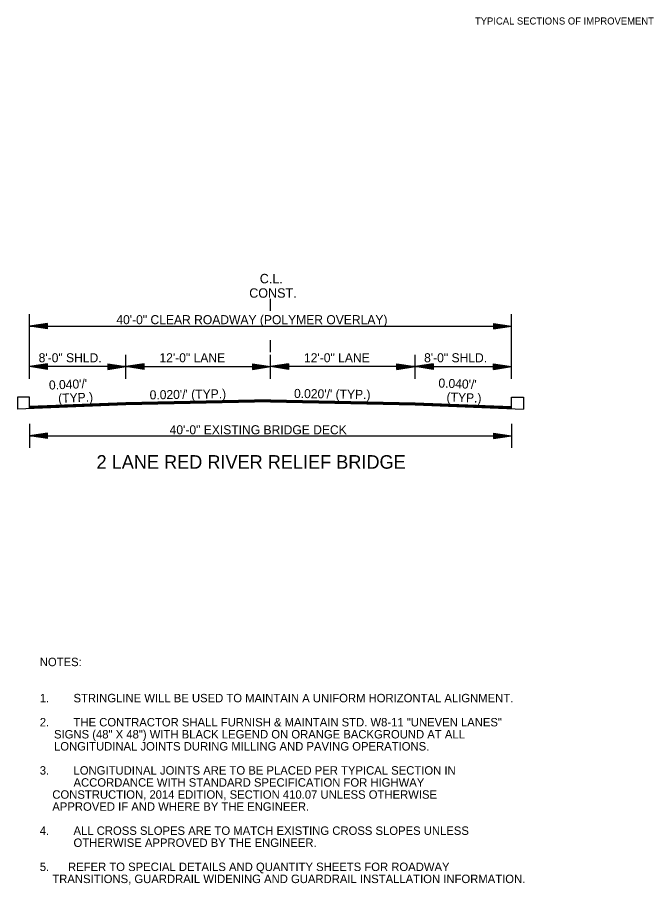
# Model space of a CAD drawing. Extents: x 545241 to 1930787, y -1971772 to 596640.
# Drawn here: x 547727 to 548255, y -1957206 to -1956486 of the extents above; entities that cross this region are included whole.
import ezdxf

# ---------------------------------------------------------------- set-up
doc = ezdxf.new("R2010")
doc.units = 0
for name, color, linetype in [('R_Border', 7, 'Continuous'), ('R_Border Notes', 7, 'Continuous'), ('R_Border Prem', 7, 'Continuous'), ('R_Draft', 7, 'Continuous')]:
    doc.layers.add(name, color=color, linetype=linetype)

msp = doc.modelspace()

# ---------------------------------------------------------------- linework, layer by layer
at = {"layer": 'R_Border'}
for p, q in [((547737.06, -1956801.11), (547726.89, -1956801.11)), ((547726.89, -1956801.11), (547726.89, -1956811.13)), ((547737.06, -1956810.72), (547737.06, -1956801.11)), ((548137.06, -1956801.31), (548147.23, -1956801.31)), ((548137.06, -1956810.72), (548137.06, -1956801.31)), ((548147.23, -1956801.31), (548147.23, -1956811.13))]:
    msp.add_line(p, q, dxfattribs=at)
at = {"layer": 'R_Draft'}
for p, q in [((547937.06, -1956729.59), (547937.06, -1956719.59)), ((547737.06, -1956785.84), (547737.06, -1956732.31)), ((548137.06, -1956785.84), (548137.06, -1956732.31)), ((547752.06, -1956740.06), (547737.06, -1956742.31)), ((547737.06, -1956742.31), (548137.06, -1956742.31)), ((547752.06, -1956744.56), (547737.06, -1956742.31)), ((547752.06, -1956740.43), (547739.56, -1956742.31)), ((547752.06, -1956744.18), (547739.56, -1956742.31)), ((547752.06, -1956740.81), (547742.14, -1956742.31)), ((547752.06, -1956743.8), (547742.14, -1956742.31)), ((547752.06, -1956741.19), (547744.64, -1956742.31)), ((547752.06, -1956743.42), (547744.64, -1956742.31)), ((547752.06, -1956741.57), (547747.18, -1956742.31)), ((547752.06, -1956743.03), (547747.18, -1956742.31)), ((547752.06, -1956741.95), (547749.69, -1956742.31)), ((547752.06, -1956742.66), (547749.69, -1956742.31)), ((547752.06, -1956744.56), (547752.06, -1956740.06)), ((548122.06, -1956740.06), (548137.06, -1956742.31)), ((548122.06, -1956740.06), (548122.06, -1956744.56)), ((548122.06, -1956740.43), (548134.55, -1956742.31)), ((548122.06, -1956740.81), (548131.97, -1956742.31)), ((548122.06, -1956741.19), (548129.48, -1956742.31)), ((548122.06, -1956741.58), (548126.93, -1956742.31)), ((548122.06, -1956741.95), (548124.43, -1956742.31)), ((548122.06, -1956744.56), (548137.06, -1956742.31)), ((548122.06, -1956743.04), (548126.93, -1956742.31)), ((548122.06, -1956743.8), (548131.97, -1956742.31)), ((548122.06, -1956744.18), (548134.55, -1956742.31)), ((548122.06, -1956743.42), (548129.48, -1956742.31)), ((548122.06, -1956742.66), (548124.43, -1956742.31)), ((547937.06, -1956763.83), (547937.06, -1956753.96)), ((547817.06, -1956785.84), (547817.06, -1956765.95)), ((547937.06, -1956785.84), (547937.06, -1956765.95)), ((548057.06, -1956785.84), (548057.06, -1956765.95)), ((547752.06, -1956773.59), (547737.06, -1956775.84)), ((547817.06, -1956775.84), (547737.06, -1956775.84)), ((547752.06, -1956778.09), (547737.06, -1956775.84)), ((547752.06, -1956773.97), (547739.56, -1956775.84)), ((547752.06, -1956777.72), (547739.56, -1956775.84)), ((547752.06, -1956774.35), (547742.14, -1956775.84)), ((547752.06, -1956777.33), (547742.14, -1956775.84)), ((547752.06, -1956774.72), (547744.64, -1956775.84)), ((547752.06, -1956776.96), (547744.64, -1956775.84)), ((547752.06, -1956775.11), (547747.18, -1956775.84)), ((547752.06, -1956776.57), (547747.18, -1956775.84)), ((547752.06, -1956775.49), (547749.69, -1956775.84)), ((547752.06, -1956776.19), (547749.69, -1956775.84)), ((547752.06, -1956778.09), (547752.06, -1956773.59)), ((547802.06, -1956773.59), (547817.06, -1956775.84)), ((547802.06, -1956773.59), (547802.06, -1956778.09)), ((547802.06, -1956773.97), (547814.55, -1956775.84)), ((547802.06, -1956774.35), (547811.97, -1956775.84)), ((547802.06, -1956774.72), (547809.48, -1956775.84)), ((547802.06, -1956775.11), (547806.93, -1956775.84)), ((547802.06, -1956775.49), (547804.43, -1956775.84)), ((547802.06, -1956778.09), (547817.06, -1956775.84)), ((547802.06, -1956776.58), (547806.93, -1956775.84)), ((547802.06, -1956777.33), (547811.97, -1956775.84)), ((547802.06, -1956777.72), (547814.55, -1956775.84)), ((547802.06, -1956776.96), (547809.48, -1956775.84)), ((547802.06, -1956776.19), (547804.43, -1956775.84)), ((547832.06, -1956773.59), (547817.06, -1956775.84)), ((547832.06, -1956778.09), (547817.06, -1956775.84)), ((547817.06, -1956775.84), (547937.06, -1956775.84)), ((547832.06, -1956773.97), (547819.56, -1956775.84)), ((547832.06, -1956777.72), (547819.56, -1956775.84)), ((547832.06, -1956774.35), (547822.14, -1956775.84)), ((547832.06, -1956777.33), (547822.14, -1956775.84)), ((547832.06, -1956774.72), (547824.64, -1956775.84)), ((547832.06, -1956776.96), (547824.64, -1956775.84)), ((547832.06, -1956775.11), (547827.18, -1956775.84)), ((547832.06, -1956776.57), (547827.18, -1956775.84)), ((547832.06, -1956775.49), (547829.69, -1956775.84)), ((547832.06, -1956776.19), (547829.69, -1956775.84)), ((547832.06, -1956778.09), (547832.06, -1956773.59)), ((547922.06, -1956773.59), (547937.06, -1956775.84)), ((547922.06, -1956773.59), (547922.06, -1956778.09)), ((547922.06, -1956773.97), (547934.55, -1956775.84)), ((547922.06, -1956774.35), (547931.97, -1956775.84)), ((547922.06, -1956774.72), (547929.48, -1956775.84)), ((547922.06, -1956775.11), (547926.93, -1956775.84)), ((547922.06, -1956775.49), (547924.43, -1956775.84)), ((547922.06, -1956778.09), (547937.06, -1956775.84)), ((547922.06, -1956776.58), (547926.93, -1956775.84)), ((547922.06, -1956777.33), (547931.97, -1956775.84)), ((547922.06, -1956777.72), (547934.55, -1956775.84)), ((547922.06, -1956776.96), (547929.48, -1956775.84)), ((547922.06, -1956776.19), (547924.43, -1956775.84)), ((547952.06, -1956773.59), (547937.06, -1956775.84)), ((548057.06, -1956775.84), (547937.06, -1956775.84)), ((547952.06, -1956778.09), (547937.06, -1956775.84)), ((547952.06, -1956773.97), (547939.56, -1956775.84)), ((547952.06, -1956777.72), (547939.56, -1956775.84)), ((547952.06, -1956774.35), (547942.14, -1956775.84)), ((547952.06, -1956777.33), (547942.14, -1956775.84)), ((547952.06, -1956774.72), (547944.64, -1956775.84)), ((547952.06, -1956776.96), (547944.64, -1956775.84)), ((547952.06, -1956775.11), (547947.18, -1956775.84)), ((547952.06, -1956776.58), (547947.18, -1956775.84)), ((547952.06, -1956775.49), (547949.69, -1956775.84)), ((547952.06, -1956776.19), (547949.69, -1956775.84)), ((547952.06, -1956773.59), (547952.06, -1956778.09)), ((548042.06, -1956773.59), (548057.06, -1956775.84)), ((548042.06, -1956778.09), (548042.06, -1956773.59)), ((548042.06, -1956773.97), (548054.55, -1956775.84)), ((548042.06, -1956774.35), (548051.97, -1956775.84)), ((548042.06, -1956774.72), (548049.48, -1956775.84)), ((548042.06, -1956775.11), (548046.93, -1956775.84)), ((548042.06, -1956775.49), (548044.43, -1956775.84)), ((548042.06, -1956778.09), (548057.06, -1956775.84)), ((548042.06, -1956776.57), (548046.93, -1956775.84)), ((548042.06, -1956777.33), (548051.97, -1956775.84)), ((548042.06, -1956777.72), (548054.55, -1956775.84)), ((548042.06, -1956776.96), (548049.48, -1956775.84)), ((548042.06, -1956776.19), (548044.43, -1956775.84)), ((548072.06, -1956773.59), (548057.06, -1956775.84)), ((548072.06, -1956778.09), (548057.06, -1956775.84)), ((548057.06, -1956775.84), (548137.06, -1956775.84)), ((548072.06, -1956773.97), (548059.56, -1956775.84)), ((548072.06, -1956777.72), (548059.56, -1956775.84)), ((548072.06, -1956774.35), (548062.14, -1956775.84)), ((548072.06, -1956777.33), (548062.14, -1956775.84)), ((548072.06, -1956774.72), (548064.64, -1956775.84)), ((548072.06, -1956776.96), (548064.64, -1956775.84)), ((548072.06, -1956775.11), (548067.18, -1956775.84)), ((548072.06, -1956776.58), (548067.18, -1956775.84)), ((548072.06, -1956775.49), (548069.69, -1956775.84)), ((548072.06, -1956776.19), (548069.69, -1956775.84)), ((548072.06, -1956773.59), (548072.06, -1956778.09)), ((548122.06, -1956773.59), (548137.06, -1956775.84)), ((548122.06, -1956778.09), (548122.06, -1956773.59)), ((548122.06, -1956773.97), (548134.55, -1956775.84)), ((548122.06, -1956774.35), (548131.97, -1956775.84)), ((548122.06, -1956774.72), (548129.48, -1956775.84)), ((548122.06, -1956775.11), (548126.93, -1956775.84)), ((548122.06, -1956775.49), (548124.43, -1956775.84)), ((548122.06, -1956778.09), (548137.06, -1956775.84)), ((548122.06, -1956776.57), (548126.93, -1956775.84)), ((548122.06, -1956777.33), (548131.97, -1956775.84)), ((548122.06, -1956777.72), (548134.55, -1956775.84)), ((548122.06, -1956776.96), (548129.48, -1956775.84)), ((548122.06, -1956776.19), (548124.43, -1956775.84)), ((547817.06, -1956807.52), (547726.89, -1956811.13)), ((547817.06, -1956805.85), (547737.06, -1956809.05)), ((547817.06, -1956806.15), (547737.06, -1956809.35)), ((547817.06, -1956806.45), (547737.06, -1956809.65)), ((547817.06, -1956806.75), (547737.06, -1956809.95)), ((547817.06, -1956807.05), (547737.06, -1956810.25)), ((547817.06, -1956807.35), (547737.06, -1956810.55)), ((547937.06, -1956803.45), (547817.06, -1956805.85)), ((547937.06, -1956803.75), (547817.06, -1956806.15)), ((547937.07, -1956804.05), (547817.06, -1956806.45)), ((547937.08, -1956804.35), (547817.06, -1956806.75)), ((547937.08, -1956804.65), (547817.06, -1956807.05)), ((547937.09, -1956804.95), (547817.06, -1956807.35)), ((547937.09, -1956805.12), (547817.06, -1956807.52)), ((547937.02, -1956805.12), (548057.06, -1956807.52)), ((547937.03, -1956804.65), (548057.06, -1956807.05)), ((547937.03, -1956804.95), (548057.06, -1956807.35)), ((547937.04, -1956804.35), (548057.06, -1956806.75)), ((547937.05, -1956803.75), (548057.06, -1956806.15)), ((547937.05, -1956804.05), (548057.06, -1956806.45)), ((547937.06, -1956803.45), (548057.06, -1956805.85)), ((548057.06, -1956805.85), (548137.06, -1956809.05)), ((548057.06, -1956806.15), (548137.06, -1956809.35)), ((548057.06, -1956806.45), (548137.06, -1956809.65)), ((548057.06, -1956806.75), (548137.06, -1956809.95)), ((548057.06, -1956807.05), (548137.06, -1956810.25)), ((548057.06, -1956807.35), (548137.06, -1956810.55)), ((548057.06, -1956807.52), (548147.23, -1956811.13)), ((547737.06, -1956823.31), (547737.06, -1956843.31)), ((548137.06, -1956823.31), (548137.06, -1956843.31)), ((547752.06, -1956831.06), (547737.06, -1956833.31)), ((547737.06, -1956833.31), (548137.06, -1956833.31)), ((547752.06, -1956835.56), (547737.06, -1956833.31)), ((547752.06, -1956831.43), (547739.56, -1956833.31)), ((547752.06, -1956835.18), (547739.56, -1956833.31)), ((547752.06, -1956831.81), (547742.14, -1956833.31)), ((547752.06, -1956834.8), (547742.14, -1956833.31)), ((547752.06, -1956832.19), (547744.64, -1956833.31)), ((547752.06, -1956834.42), (547744.64, -1956833.31)), ((547752.06, -1956832.57), (547747.18, -1956833.31)), ((547752.06, -1956834.03), (547747.18, -1956833.31)), ((547752.06, -1956832.95), (547749.69, -1956833.31)), ((547752.06, -1956833.66), (547749.69, -1956833.31)), ((547752.06, -1956835.56), (547752.06, -1956831.06)), ((548122.06, -1956831.06), (548137.06, -1956833.31)), ((548122.06, -1956831.06), (548122.06, -1956835.56)), ((548122.06, -1956831.43), (548134.55, -1956833.31)), ((548122.06, -1956831.81), (548131.97, -1956833.31)), ((548122.06, -1956832.19), (548129.48, -1956833.31)), ((548122.06, -1956832.58), (548126.93, -1956833.31)), ((548122.06, -1956832.95), (548124.43, -1956833.31)), ((548122.06, -1956835.56), (548137.06, -1956833.31)), ((548122.06, -1956834.04), (548126.93, -1956833.31)), ((548122.06, -1956834.8), (548131.97, -1956833.31)), ((548122.06, -1956835.18), (548134.55, -1956833.31)), ((548122.06, -1956834.42), (548129.48, -1956833.31)), ((548122.06, -1956833.66), (548124.43, -1956833.31))]:
    msp.add_line(p, q, dxfattribs=at)

# ---------------------------------------------------------------- texts
at = {"layer": 'R_Border Notes'}
for s, p in [('NOTES: ', (547745.53, -1957024.39)), ('1.', (547745.53, -1957054.39)), ('STRINGLINE WILL BE USED TO MAINTAIN A UNIFORM HORIZONTAL ALIGNMENT.', (547773.53, -1957054.39)), ('2.', (547745.53, -1957074.39)), ('THE CONTRACTOR SHALL FURNISH & MAINTAIN STD. W8-11 "UNEVEN LANES" ', (547773.53, -1957074.39)), ('    SIGNS (48" X 48") WITH BLACK LEGEND ON ORANGE BACKGROUND AT ALL ', (547746.93, -1957084.39)), ('    LONGITUDINAL JOINTS DURING MILLING AND PAVING OPERATIONS.', (547746.93, -1957094.39)), ('3.', (547745.53, -1957114.39)), ('LONGITUDINAL JOINTS ARE TO BE PLACED PER TYPICAL SECTION IN ', (547773.53, -1957114.39)), ('ACCORDANCE WITH STANDARD SPECIFICATION FOR HIGHWAY', (547773.53, -1957124.39)), ('    CONSTRUCTION, 2014 EDITION, SECTION 410.07 UNLESS OTHERWISE', (547745.53, -1957134.39)), ('    APPROVED IF AND WHERE BY THE ENGINEER.', (547745.53, -1957144.39)), ('4.', (547745.53, -1957164.39)), ('ALL CROSS SLOPES ARE TO MATCH EXISTING CROSS SLOPES UNLESS ', (547773.53, -1957164.39)), ('OTHERWISE APPROVED BY THE ENGINEER.', (547773.53, -1957174.39)), ('5.      REFER TO SPECIAL DETAILS AND QUANTITY SHEETS FOR ROADWAY', (547745.53, -1957194.39)), ('    TRANSITIONS, GUARDRAIL WIDENING AND GUARDRAIL INSTALLATION INFORMATION.', (547745.53, -1957204.39))]:
    msp.add_text(s, height=7, dxfattribs=at).set_placement(p)
at = {"layer": 'R_Border Prem'}
msp.add_text('TYPICAL SECTIONS OF IMPROVEMENT', height=5.862, rotation=360, dxfattribs=at).set_placement((548106.81, -1956491.97))
at = {"layer": 'R_Draft'}
for s, height, p in [('C.L.', 7.8, (547928.16, -1956706.7)), ('CONST.', 7.8, (547919.38, -1956718.66)), ('40\'-0" CLEAR ROADWAY (POLYMER OVERLAY)', 7.5, (547809.09, -1956740.63)), ('8\'-0" SHLD.', 7.5, (547744.58, -1956772.24)), ('12\'-0" LANE', 7.5, (547844.87, -1956772.24)), ('12\'-0" LANE', 7.5, (547964.87, -1956772.24)), ('8\'-0" SHLD.', 7.5, (548064.58, -1956772.24)), ('40\'-0" EXISTING BRIDGE DECK', 7.5, (547853.32, -1956831.98)), ('2 LANE RED RIVER RELIEF BRIDGE', 11.25, (547792.67, -1956860.55))]:
    msp.add_text(s, height=height, dxfattribs=at).set_placement(p)
for s, rotation, p in [("0.040'/' ", 2.29061, (547753.28, -1956794.93)), ("0.040'/' ", 357.70939, (548076.34, -1956793.15)), ("0.020'/' (TYP.)", 0.87191, (547836.78, -1956803.03)), ("0.020'/' (TYP.)", 359.12809, (547956.55, -1956801.8)), ('(TYP.)', 2.29061, (547760.93, -1956805.89)), ('(TYP.)', 357.70939, (548083.09, -1956804.68))]:
    msp.add_text(s, height=7.5, rotation=rotation, dxfattribs=at).set_placement(p)

doc.saveas('drawing.dxf')
